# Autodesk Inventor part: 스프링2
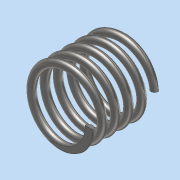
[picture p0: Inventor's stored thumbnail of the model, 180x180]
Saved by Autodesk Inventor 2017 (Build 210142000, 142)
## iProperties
Part Number: 스프링2
Material: 스테인레스 스틸
Document SubType Name: Modeling
Designer: MRC
Density: 8 g/cm^3
Appearance: 반연마
Mass: 6.55763 g
Surface Area: 16.7052 cm^2
Volume: 0.819704 cm^3
Author: MRC
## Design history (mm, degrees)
sketch "스케치1"
  geometry: L1 (0, 0)-(0, 17.5); L2 (0, 0)-(8.5, 0); L3 (0, 17.5)-(8.5, 17.5); C1 r 1 at (8.5, 0)
  constraints: 6 end point, 1 centre point, 1 coincident, 1 horizontal, 1 vertical, 1 vertical alignment
  dimensions: "d0" = 17.5 distance of L1.start L1.end (derived); "d1" = 17 diameter of L2.end L1; "d2" = 2 diameter of C1
feature "코일1" pitch "d3" = 10; turns "d5" = 5; dims "d4" = 17.5 (= d0), "d6" = 0, angle "d7" = 90 deg, angle "d8" = 90 deg, "d9" = 0, "d10" = 0
sketch "스케치2"
  geometry: L1 (17.5, 17.5)-(0, 17.5); L2 (0, 17.5)-(0, -17.5); L3 (0, -17.5)-(17.5, -17.5); L4 (17.5, -17.5)-(17.5, 17.5); 2 further points
  constraints: 8 end point, 2 parallel, 1 coincident, 1 horizontal, 1 midpoint, 1 perpendicular
  dimensions: "d11" = 17.5 distance of L2.end L3.end (= d0); "d12" = 35 distance between parallel lines of L1 L3
extrude "돌출2" sketch "스케치2" stored distance "d15" = 0; taper "d16" = 0 deg
node "솔리드1"
